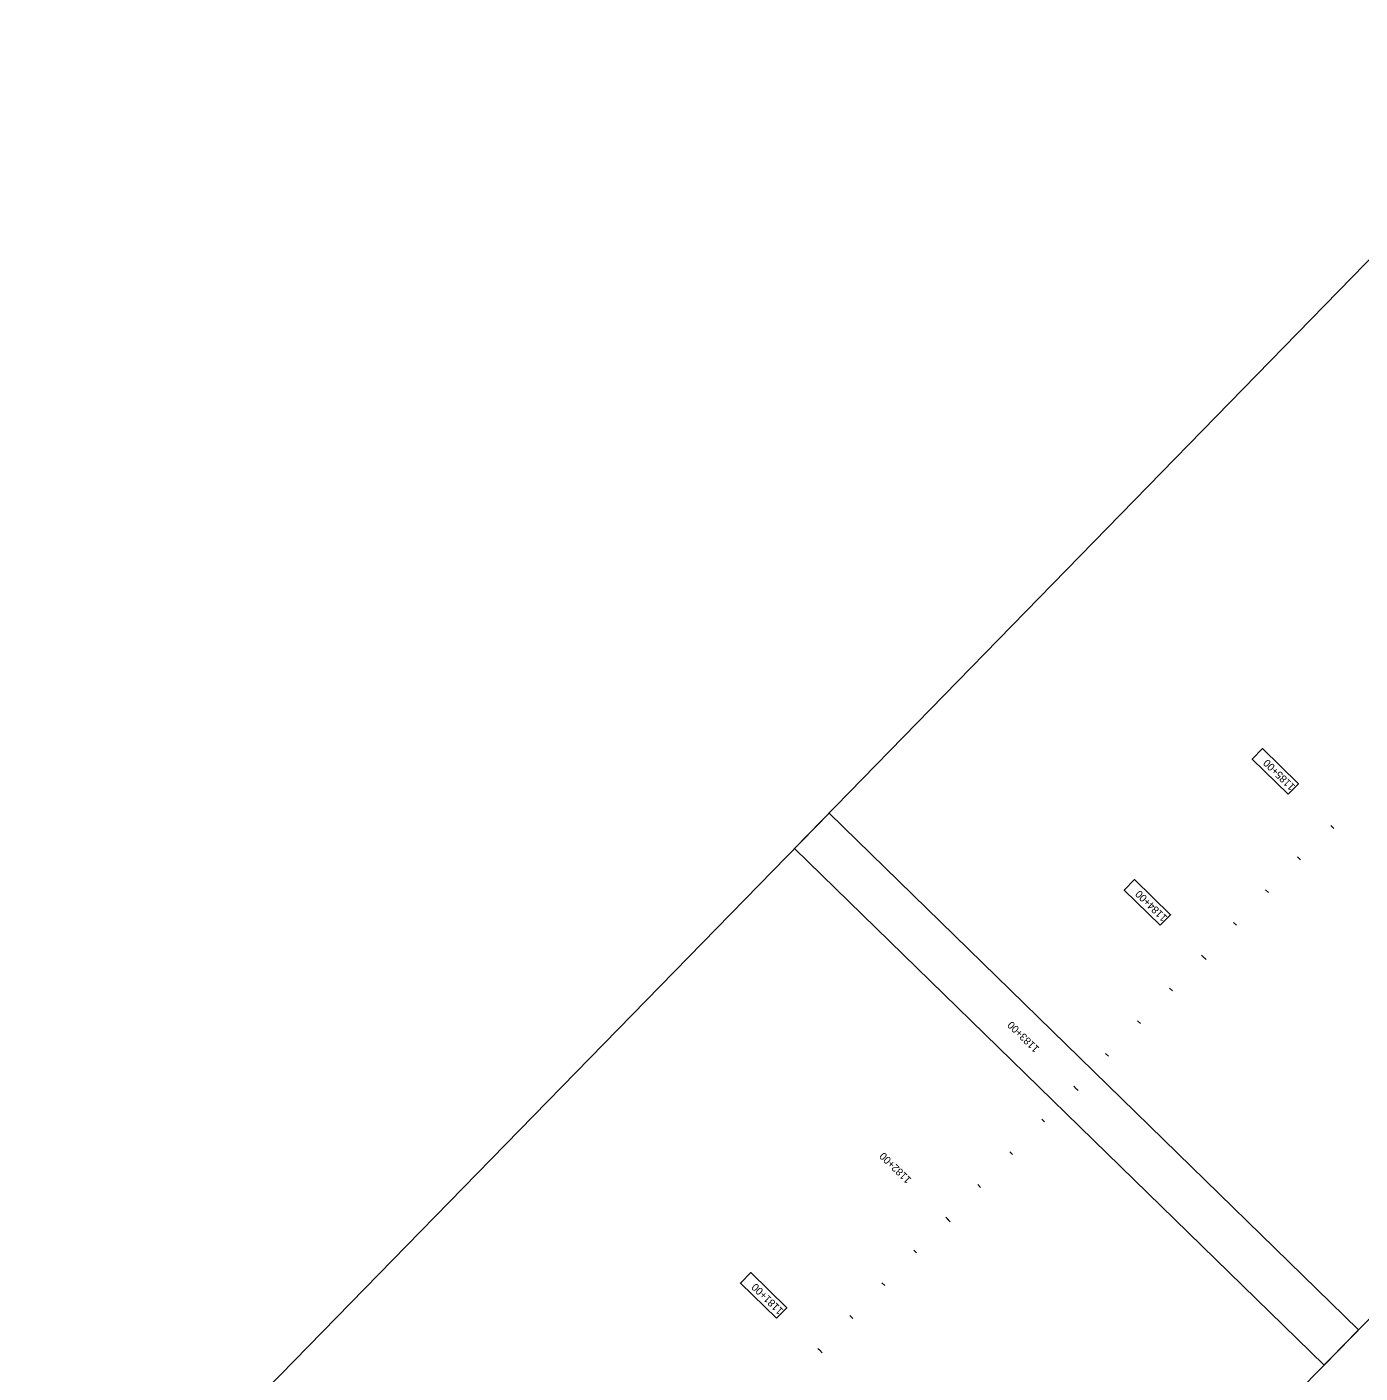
# Model space of a CAD drawing. Extents: x 19420655 to 19421801, y 7630893 to 7632053.
# Drawn here: x 19420655 to 19421383, y 7631318 to 7632053 of the extents above; entities that cross this region are included whole.
import ezdxf

# ---------------------------------------------------------------- set-up
doc = ezdxf.new("R2010")
doc.units = 0
for name, color, linetype in [('Level 1', 7, 'Continuous'), ('Level 4', 7, 'Continuous'), ('Level 5', 7, 'Continuous'), ('Level 6', 7, 'Continuous')]:
    doc.layers.add(name, color=color, linetype=linetype)

msp = doc.modelspace()

# ---------------------------------------------------------------- linework, layer by layer
at = {"layer": 'Level 1'}
for p, q in [((19421366.53, 7631617.05), (19421368.28, 7631615.34)), ((19421297.57, 7631544.62), (19421296, 7631546.15)), ((19421227.73, 7631473.05), (19421226.16, 7631474.58)), ((19421157.89, 7631401.48), (19421156.32, 7631403.01)), ((19421088.05, 7631329.91), (19421086.48, 7631331.44))]:
    msp.add_line(p, q, dxfattribs=at)
at = {"layer": 'Level 4'}
for p, q in [((19421366.53, 7631617.05), (19421368.28, 7631615.34)), ((19421349.95, 7631598.3), (19421348.38, 7631599.83)), ((19421332.49, 7631580.41), (19421330.92, 7631581.94)), ((19421315.03, 7631562.52), (19421313.46, 7631564.04)), ((19421296.69, 7631545.48), (19421298.44, 7631543.77)), ((19421280.11, 7631526.73), (19421278.54, 7631528.26)), ((19421262.65, 7631508.84), (19421261.08, 7631510.36)), ((19421245.19, 7631490.95), (19421243.62, 7631492.47)), ((19421226.85, 7631473.91), (19421228.6, 7631472.2)), ((19421210.27, 7631455.16), (19421208.7, 7631456.69)), ((19421192.81, 7631437.27), (19421191.24, 7631438.79)), ((19421175.35, 7631419.38), (19421173.78, 7631420.9)), ((19421157.01, 7631402.34), (19421158.76, 7631400.63)), ((19421140.43, 7631383.59), (19421138.86, 7631385.12)), ((19421122.97, 7631365.7), (19421121.4, 7631367.22)), ((19421105.51, 7631347.81), (19421103.94, 7631349.33)), ((19421087.17, 7631330.77), (19421088.92, 7631329.06))]:
    msp.add_line(p, q, dxfattribs=at)
at = {"layer": 'Level 5'}
for points in [[(19421073.73, 7631604.47), (19421511.62, 7632053.22), (19421800.77, 7631771.06), (19421362.87, 7631322.32)], [(19420654.69, 7631175.05), (19421092.58, 7631623.79), (19421381.73, 7631341.64), (19420943.83, 7630892.89)]]:
    msp.add_lwpolyline(points, close=True, dxfattribs=at)
at = {"layer": 'Level 6'}
for points in [[(19421343.29, 7631634.14), (19421348.88, 7631639.86), (19421329.2, 7631659.07), (19421323.61, 7631653.34)], [(19421273.45, 7631562.57), (19421279.04, 7631568.29), (19421259.36, 7631587.5), (19421253.77, 7631581.77)], [(19421063.93, 7631347.85), (19421069.52, 7631353.58), (19421049.84, 7631372.79), (19421044.25, 7631367.06)]]:
    msp.add_lwpolyline(points, close=True, dxfattribs=at)

# ---------------------------------------------------------------- texts
at = {"layer": 'Level 1'}
msp.add_text('1185+00', height=4.08, rotation=135.70104, dxfattribs=at).set_placement((19421347.36, 7631638.61))
at = {"layer": 'Level 4'}
for s, p in [('1185+00', (19421347.36, 7631638.61)), ('1184+00', (19421277.52, 7631567.04)), ('1183+00', (19421207.68, 7631495.47)), ('1182+00', (19421137.84, 7631423.9)), ('1181+00', (19421068, 7631352.33))]:
    msp.add_text(s, height=4.08, rotation=135.70104, dxfattribs=at).set_placement(p)

doc.saveas('drawing.dxf')
